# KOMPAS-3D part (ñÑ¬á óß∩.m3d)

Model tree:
1. Эскиз:1
2. Операция выдавливания:1
     Расстояние 1 = 0.6
3. Эскиз:2
4. Вырезать элемент выдавливания:1
     Толщина стенки 1 = 3; Толщина стенки 2 = 3; Расстояние 1 = 10
5. Эскиз:3
6. Вырезать элемент выдавливания:2
     Толщина стенки 1 = 3; Толщина стенки 2 = 3; Расстояние 1 = 10
7. Эскиз:4
8. Вырезать элемент выдавливания:3
     Толщина стенки 1 = 3; Толщина стенки 2 = 3; Расстояние 1 = 10
9. Эскиз:5
10. Вырезать элемент выдавливания:4
     Расстояние 1 = 10
